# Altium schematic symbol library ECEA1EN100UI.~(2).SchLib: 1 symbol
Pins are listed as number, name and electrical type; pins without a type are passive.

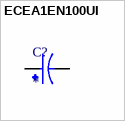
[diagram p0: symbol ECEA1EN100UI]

## ECEA1EN100UI
designator C?
10µF 25V Aluminum Electrolytic Capacitors Radial, Dia-5mm, Hight-; MF: Panasonic; MP: ECEA1EN100UI
footprint CAPPRD250W50D500H1100
pins: N, P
